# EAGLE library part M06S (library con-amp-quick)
AMP QUICK CONNECTOR
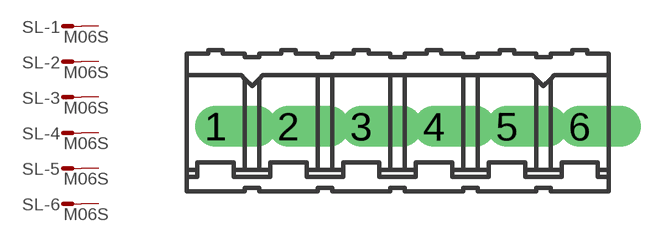
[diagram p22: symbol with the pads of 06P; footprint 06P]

Designator prefix SL; gates -1=M -2=M -3=M -4=M -5=M -6=M

## M06S  [06P]
1  -1:S  pas
2  -2:S  pas
3  -3:S  pas
4  -4:S  pas
5  -5:S  pas
6  -6:S  pas

## Footprint 06P (pad centres in mm)
AMP QUICK CONNECTOR
drill 0.914 offset: 1 -6.35,0; 2 -3.81,0; 3 -1.27,0; 4 1.27,0; 5 3.81,0; 6 6.35,0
